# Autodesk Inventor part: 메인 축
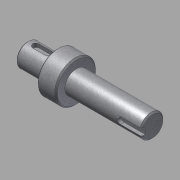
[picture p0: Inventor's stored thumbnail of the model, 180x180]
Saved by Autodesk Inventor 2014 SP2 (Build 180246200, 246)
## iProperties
Created: 2014-10
Part Number: 메인 축
Document SubType Name: Modeling
Designer: KYOUNG IL JANG
Density: 7.86 g/cm^3
Mass: 230.24 g
Surface Area: 74.3518 cm^2
Volume: 29.2926 cm^3
Material: 강철, 연강
Appearance: 금속-강(스테인리스, 브러시됨)
Author: SeoGD™ [www.esajin.kr]
Revision Number: 1
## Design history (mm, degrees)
sketch "스케치1"
  geometry: L1 (10.497, -57.5)-(102.497, -57.5); L2 (10.497, -66)-(32.497, -66); L3 (32.497, -72.5)-(46.5, -72.5); L4 (46.5, -66)-(102.497, -66); L5 (102.497, -66)-(102.497, -57.5); L6 (10.497, -66)-(10.497, -57.5); L7 (46.5, -69.749)-(46.5, -45.251) reference; L8 (46.5, -72.5)-(46.5, -66); L9 (32.497, -72.5)-(32.497, -66); L10 (32.497, -35)-(32.497, -80) reference; 2 further points
  constraints: 16 end point, 2 parallel, 2 perpendicular, 2 point on line, 1 collinear, 1 horizontal, 1 midpoint
  dimensions: "d0" = 17 diameter of L4 L1; "d1" = 30 diameter of L3 L1; "d2" = 22 distance of L2.start L2.end; "d3" = 55.99692 distance of L4.start L4.end (derived); "d5" = 17 diameter of L2 L1; "d19" = 70 distance between parallel lines of L5 L9
revolve "회전1" sketch "스케치1" stored, may be unused: angle "d4" = 90 deg
chamfer "모따기1" distance "d6" = 1; stored, may be unused: second distance "d7" = 2, angle "d8" = 45 deg
node "작업 평면1"
sketch "스케치2"
  geometry: L1 (-11, -7.5)-(-11, 7.5) reference; L2 (-4.5, 2.5)-(4.5, 2.5); L3 (4.5, -2.5)-(-4.5, -2.5); A1 r 2.5 centre (4.5, 0) between (4.5, -2.5) and (4.5, 2.5); A2 r 2.5 centre (-4.5, 0) between (-4.5, 2.5) and (-4.5, -2.5); 2 further points
  constraints: 4 end point, 4 point on circle, 4 tangent, 2 centre point, 1 horizontal alignment, 1 midpoint, 1 parallel, 1 perpendicular
  dimensions: "d9" = 5 distance between parallel lines of L3 L2; "d10" = 14 dimension on A1 A2; "d11" = 4 distance edge to line of A2 L1
extrude "돌출1" cut sketch "스케치2" distance "d12" = 3; taper "d13" = 0 deg
node "작업 평면2"
sketch "스케치3"
  geometry: L1 (27.998, 7.5)-(27.998, -7.5) reference; L2 (27.998, 2.5)-(12.498, 2.5); L3 (12.498, -2.5)-(27.998, -2.5); A1 r 2.5 centre (12.498, 0) between (12.498, 2.5) and (12.498, -2.5); 2 further points
  constraints: 4 end point, 2 perpendicular, 2 point on circle, 2 point on line, 2 tangent, 1 centre point, 1 horizontal alignment, 1 midpoint
  dimensions: "d14" = 5 distance between parallel lines of L3 L2; "d15" = 18 dimension on A1 L1
extrude "돌출2" cut sketch "스케치3" distance "d16" = 3; taper "d17" = 0 deg
node "솔리드1"
node "참조4"
node "참조5"
